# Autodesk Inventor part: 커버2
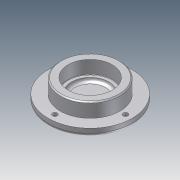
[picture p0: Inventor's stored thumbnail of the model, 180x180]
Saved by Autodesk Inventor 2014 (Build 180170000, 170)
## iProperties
Company: 한국ATC센터
Created: 2014-10
Part Number: 커버2
Document SubType Name: Modeling
Designer: KYOUNG IL JANG
Density: 1 g/cm^3
Mass: 44.7286 g
Surface Area: 161.165 cm^2
Volume: 44.7286 cm^3
Material: Generic
Appearance: Default
Author: KYOUNG IL JANG
Revision Number: 1
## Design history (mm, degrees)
sketch "스케치1"
  geometry: C1 r 38 at (0, 0); 1 further point
  constraints: 1 centre point, 1 coincident
  dimensions: "d0" = 76 diameter of C1
extrude "돌출1" new body sketch "스케치1" distance "d1" = 7; taper "d2" = 0 deg
sketch "스케치2"
  geometry: C1 r 27 at (0, 0); 1 further point
  constraints: 1 centre point, 1 coincident
  dimensions: "d3" = 54 diameter of C1
extrude "돌출2" join sketch "스케치2" distance "d4" = 13; taper "d5" = 0 deg
hole "구멍2" diameter "d20" = 34; stored, may be unused: countersink angle "d24" = 90 deg, drill point angle "d26" = 0 deg; dims "d18" = 10, "d19" = 10, "d21" = 6, "d22" = 40, "d23" = 12, "d25" = 3
fillet "모깎기2" dims "d34" = 3
fillet "모깎기1" dims "d27" = 0.3
chamfer "모따기1" distance "d28" = 1; stored, may be unused: second distance "d29" = 2, angle "d30" = 45 deg
sketch "스케치4" dims "d35" = 64
  geometry: 3 further points
  constraints: 2 horizontal alignment, 1 coincident, 2 other
hole "구멍3" sketch "스케치4" diameter "d36" = 4.5; stored, may be unused: countersink angle "d40" = 90 deg, drill point angle "d42" = 118 deg; dims "d37" = 6, "d38" = 8, "d39" = 4.4, "d41" = 13
node "솔리드1"
pattern_circular "원형 패턴1" dims angle "d44" = 360 deg
